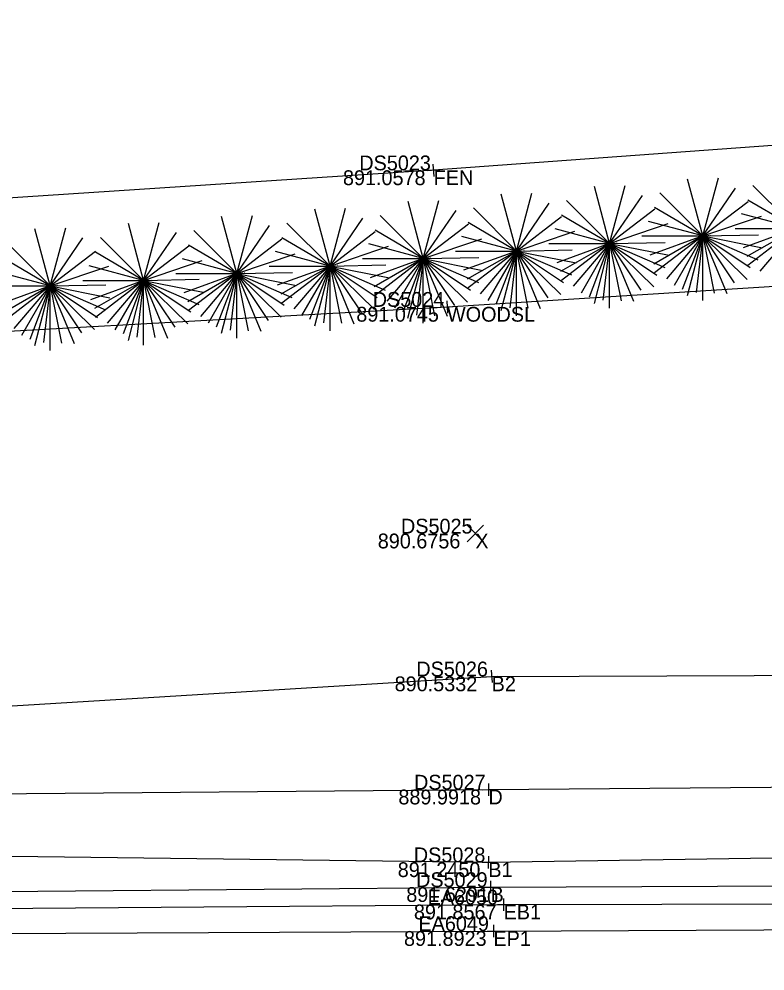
# Model space of a CAD drawing. Extents: x 179044 to 189691, y 286531 to 301257.
# Drawn here: x 179842.3 to 179902.7, y 300591.8 to 300668.9 of the extents above; entities that cross this region are included whole.
import ezdxf

# ---------------------------------------------------------------- set-up
doc = ezdxf.new("R2010")
doc.units = 0
for name, color, linetype in [('DR_X_Ditch', 7, 'Continuous'), ('PV_X_EOP', 7, 'Continuous'), ('PV_X_Shoulder_Aggregate', 7, 'Continuous'), ('RD_X_Fence', 7, 'Continuous'), ('SV_X_Break_Lines', 7, 'Continuous'), ('SV_X_Random_Point', 7, 'Continuous'), ('SV_X_Shot_Marker', 7, 'Continuous'), ('SV_X_Text_Comment', 7, 'Continuous'), ('SV_X_Text_Elevation', 7, 'Continuous'), ('SV_X_Text_Name', 7, 'Continuous'), ('VG_X_Cells', 7, 'Continuous'), ('VG_X_Text', 7, 'Continuous'), ('VG_X_Tree_Line_Rt', 7, 'Continuous')]:
    doc.layers.add(name, color=color, linetype=linetype)

msp = doc.modelspace()

# ---------------------------------------------------------------- linework, layer by layer
at = {"layer": 'DR_X_Ditch'}
msp.add_lwpolyline([(179564.56, 300599.962), (179672.339, 300603.26), (179771.172, 300605.494), (179880.337, 300606.441), (179984.937, 300607.328), (180077.947, 300608.965), (180127.19, 300616.843), (180132.045, 300619.573), (180144.286, 300623.545), (180155.547, 300629.29), (180160.465, 300633.547)], dxfattribs=at)
at = {"layer": 'PV_X_EOP'}
msp.add_lwpolyline([(179370.831, 300591.751), (179475.585, 300592.875), (179659.265, 300594.122), (179770.991, 300594.472), (179880.742, 300594.985), (179984.71, 300595.495), (180079.288, 300595.313), (180129.921, 300597.382), (180139.474, 300598.239), (180154.233, 300602.666), (180170.463, 300611.587), (180179.633, 300620.691), (180184.59, 300626.615), (180188.342, 300633.535), (180190.62, 300639.725), (180171.316, 300693.382), (180137.201, 300785.062), (180098.417, 300888.791)], dxfattribs=at)
at = {"layer": 'PV_X_Shoulder_Aggregate'}
msp.add_lwpolyline([(179563.565, 300594.924), (179658.987, 300595.359), (179770.596, 300596.259), (179881.565, 300597.129), (179984.257, 300597.357), (180079.139, 300597.322), (180129.307, 300600.299), (180139.964, 300601.425), (180153.02, 300605.118), (180169.97, 300613.883), (180177.635, 300623.691), (180181.654, 300635.111), (180182.998, 300649.235), (180167.771, 300692.69), (180134.639, 300784.201), (180095.484, 300888.508)], dxfattribs=at)
at = {"layer": 'RD_X_Fence'}
msp.add_lwpolyline([(180033.616, 300896.161), (180069.423, 300800.637), (180103.118, 300709.458), (180117.129, 300674.9), (180112.616, 300673.011), (180037.359, 300667.77), (179974.547, 300663.799), (179875.902, 300656.609), (179766.558, 300649.439), (179668.068, 300642.7), (179565.54, 300636.358)], dxfattribs=at)
at = {"layer": 'SV_X_Break_Lines'}
for points in [[(179564.638, 300606.986), (179671.768, 300606.922), (179771.087, 300608.912), (179880.599, 300615.611), (179986.884, 300616.02), (180078.033, 300615.521), (180124.742, 300624.492), (180128.289, 300624.221), (180137.303, 300629.118), (180148.459, 300633.708), (180154.503, 300636.496), (180146.307, 300651.241), (180135.969, 300673.811), (180118.542, 300716.074), (180095.911, 300772.35), (180076.611, 300824.96), (180047.5, 300900.199)], [(179564.191, 300598.682), (179770.809, 300601.942), (179880.33, 300600.557), (179984.707, 300602.17), (180076.298, 300602.513), (180129.447, 300605.473), (180133.823, 300610.665), (180143.543, 300612.063), (180154.911, 300619.358), (180168.807, 300625.749), (180172.898, 300631.66), (180174.527, 300641.071), (180168.307, 300660.619), (180157.537, 300688.57), (180123.865, 300779.294), (180087.271, 300883.216)], [(179564.385, 300595.92), (179672.75, 300596.68), (179770.459, 300597.562), (179880.51, 300598.544), (179984.703, 300599.007), (180076.342, 300598.773), (180129.476, 300602.027), (180135.94, 300603.814), (180151.807, 300606.879), (180162.976, 300612.722)]]:
    msp.add_lwpolyline(points, dxfattribs=at)
at = {"layer": 'SV_X_Random_Point'}
for p, q in [((179878.613, 300626.516), (179879.946, 300627.851)), ((179878.613, 300627.851), (179879.946, 300626.516))]:
    msp.add_line(p, q, dxfattribs=at)
at = {"layer": 'SV_X_Shot_Marker'}
for p, q in [((179876.401, 300656.644), (179875.403, 300656.575)), ((179875.936, 300656.11), (179875.867, 300657.108)), ((179875.902, 300656.609), (179875.902, 300656.609)), ((179876.954, 300646.049), (179877.009, 300645.05)), ((179876.482, 300645.522), (179877.481, 300645.577)), ((179876.981, 300645.549), (179876.981, 300645.549)), ((179880.1, 300615.581), (179881.098, 300615.642)), ((179880.569, 300616.11), (179880.63, 300615.112)), ((179880.599, 300615.611), (179880.599, 300615.611)), ((179879.837, 300606.436), (179880.837, 300606.445)), ((179880.332, 300606.941), (179880.341, 300605.941)), ((179880.337, 300606.441), (179880.337, 300606.441)), ((179880.336, 300601.057), (179880.323, 300600.057)), ((179879.83, 300600.563), (179880.83, 300600.55)), ((179880.33, 300600.557), (179880.33, 300600.557)), ((179880.505, 300599.044), (179880.514, 300598.044)), ((179880.01, 300598.54), (179881.01, 300598.549)), ((179880.51, 300598.544), (179880.51, 300598.544)), ((179881.065, 300597.125), (179882.064, 300597.133)), ((179881.561, 300597.629), (179881.568, 300596.629)), ((179881.565, 300597.129), (179881.565, 300597.129)), ((179880.242, 300594.983), (179881.242, 300594.988)), ((179880.74, 300595.485), (179880.745, 300594.485)), ((179880.742, 300594.985), (179880.742, 300594.985))]:
    msp.add_line(p, q, dxfattribs=at)
at = {"layer": 'VG_X_Cells'}
for p, q in [((179897.709, 300651.29), (179896.474, 300655.904)), ((179897.709, 300651.29), (179898.966, 300655.989)), ((179890.158, 300650.681), (179888.923, 300655.294)), ((179890.158, 300650.681), (179891.415, 300655.379)), ((179897.709, 300651.29), (179900.364, 300655.175)), ((179905.26, 300651.9), (179901.77, 300655.386)), ((179875.057, 300649.463), (179876.313, 300654.161)), ((179882.608, 300650.072), (179881.373, 300654.685)), ((179882.608, 300650.072), (179883.864, 300654.77)), ((179890.158, 300650.681), (179886.668, 300654.168)), ((179890.158, 300650.681), (179892.813, 300654.566)), ((179897.709, 300651.29), (179894.219, 300654.777)), ((179897.709, 300651.29), (179901.366, 300654.095)), ((179905.26, 300651.9), (179901.353, 300654.196)), ((179867.506, 300648.854), (179866.271, 300653.467)), ((179867.506, 300648.854), (179868.763, 300653.552)), ((179875.057, 300649.463), (179873.822, 300654.076)), ((179875.057, 300649.463), (179877.712, 300653.348)), ((179882.608, 300650.072), (179879.118, 300653.559)), ((179882.608, 300650.072), (179885.263, 300653.957)), ((179890.158, 300650.681), (179893.815, 300653.486)), ((179897.709, 300651.29), (179893.802, 300653.587)), ((179859.955, 300648.244), (179858.72, 300652.858)), ((179859.955, 300648.244), (179861.212, 300652.943)), ((179867.506, 300648.854), (179870.161, 300652.739)), ((179875.057, 300649.463), (179871.567, 300652.949)), ((179882.608, 300650.072), (179886.264, 300652.877)), ((179890.158, 300650.681), (179886.252, 300652.978)), ((179897.709, 300651.29), (179902.446, 300652.897)), ((179905.26, 300651.9), (179900.847, 300653.083)), ((179844.836, 300647.249), (179843.601, 300651.862)), ((179844.836, 300647.249), (179846.093, 300651.947)), ((179852.4, 300647.692), (179851.165, 300652.305)), ((179852.4, 300647.692), (179853.657, 300652.39)), ((179859.955, 300648.244), (179862.61, 300652.129)), ((179867.506, 300648.854), (179864.016, 300652.34)), ((179875.057, 300649.463), (179878.713, 300652.268)), ((179882.608, 300650.072), (179878.701, 300652.369)), ((179890.158, 300650.681), (179885.745, 300651.864)), ((179890.158, 300650.681), (179894.895, 300652.288)), ((179897.709, 300651.29), (179893.296, 300652.474)), ((179900.325, 300651.9), (179905.26, 300651.9)), ((179905.26, 300651.9), (179900.97, 300650.338)), ((179905.26, 300651.9), (179901.277, 300649.618)), ((179905.26, 300651.9), (179901.353, 300648.905)), ((179905.26, 300651.9), (179902.315, 300648.433)), ((179844.836, 300647.249), (179847.491, 300651.134)), ((179852.4, 300647.692), (179848.91, 300651.178)), ((179852.4, 300647.692), (179855.055, 300651.577)), ((179859.955, 300648.244), (179856.465, 300651.731)), ((179859.955, 300648.244), (179863.612, 300651.049)), ((179867.506, 300648.854), (179863.599, 300651.15)), ((179867.506, 300648.854), (179871.163, 300651.659)), ((179875.057, 300649.463), (179871.15, 300651.759)), ((179875.057, 300649.463), (179879.793, 300651.069)), ((179882.608, 300650.072), (179878.194, 300651.255)), ((179882.608, 300650.072), (179887.344, 300651.679)), ((179892.774, 300651.29), (179897.709, 300651.29)), ((179897.709, 300651.29), (179893.419, 300649.729)), ((179897.709, 300651.29), (179893.726, 300649.009)), ((179897.709, 300651.29), (179893.802, 300648.295)), ((179897.709, 300651.29), (179894.764, 300647.824)), ((179897.709, 300651.29), (179895.391, 300647.275)), ((179897.709, 300651.29), (179896.044, 300646.95)), ((179897.709, 300651.29), (179896.446, 300646.434)), ((179897.709, 300651.29), (179897.167, 300646.699)), ((179897.709, 300651.29), (179902.219, 300651.382)), ((179897.709, 300646.05), (179897.709, 300651.29)), ((179897.709, 300651.29), (179898.631, 300646.654)), ((179897.709, 300651.29), (179899.642, 300646.622)), ((179897.709, 300651.29), (179900.246, 300647.497)), ((179897.709, 300651.29), (179901.297, 300647.769)), ((179897.709, 300651.29), (179901.531, 300648.735)), ((179897.709, 300651.29), (179902.174, 300649.349)), ((179897.709, 300651.29), (179902.537, 300650.332)), ((179844.836, 300647.249), (179841.346, 300650.736)), ((179852.4, 300647.692), (179856.057, 300650.497)), ((179859.955, 300648.244), (179856.049, 300650.541)), ((179867.506, 300648.854), (179872.243, 300650.46)), ((179875.057, 300649.463), (179870.643, 300650.646)), ((179885.223, 300650.681), (179890.158, 300650.681)), ((179890.158, 300650.681), (179885.868, 300649.119)), ((179890.158, 300650.681), (179886.175, 300648.399)), ((179890.158, 300650.681), (179886.252, 300647.686)), ((179890.158, 300650.681), (179887.213, 300647.214)), ((179890.158, 300650.681), (179887.84, 300646.666)), ((179890.158, 300650.681), (179888.493, 300646.341)), ((179890.158, 300650.681), (179888.895, 300645.824)), ((179890.158, 300650.681), (179889.617, 300646.089)), ((179890.158, 300650.681), (179894.668, 300650.773)), ((179890.158, 300645.441), (179890.158, 300650.681)), ((179890.158, 300650.681), (179891.08, 300646.044)), ((179890.158, 300650.681), (179892.092, 300646.013)), ((179890.158, 300650.681), (179892.695, 300646.888)), ((179890.158, 300650.681), (179893.747, 300647.159)), ((179890.158, 300650.681), (179893.98, 300648.126)), ((179890.158, 300650.681), (179894.623, 300648.739)), ((179890.158, 300650.681), (179894.987, 300649.723)), ((179844.836, 300647.249), (179840.93, 300649.546)), ((179844.836, 300647.249), (179848.493, 300650.054)), ((179852.4, 300647.692), (179848.493, 300649.988)), ((179859.955, 300648.244), (179864.692, 300649.851)), ((179867.506, 300648.854), (179863.093, 300650.037)), ((179875.057, 300649.463), (179879.567, 300649.554)), ((179877.673, 300650.072), (179882.608, 300650.072)), ((179882.608, 300650.072), (179878.318, 300648.51)), ((179882.608, 300650.072), (179878.624, 300647.79)), ((179882.608, 300650.072), (179878.701, 300647.077)), ((179882.608, 300650.072), (179879.663, 300646.605)), ((179882.608, 300650.072), (179880.289, 300646.057)), ((179882.608, 300650.072), (179880.943, 300645.732)), ((179882.608, 300650.072), (179881.344, 300645.215)), ((179882.608, 300650.072), (179882.066, 300645.48)), ((179882.608, 300650.072), (179887.118, 300650.164)), ((179882.608, 300644.832), (179882.608, 300650.072)), ((179882.608, 300650.072), (179883.529, 300645.435)), ((179882.608, 300650.072), (179884.541, 300645.404)), ((179882.608, 300650.072), (179885.144, 300646.279)), ((179882.608, 300650.072), (179886.196, 300646.55)), ((179882.608, 300650.072), (179886.429, 300647.517)), ((179882.608, 300650.072), (179887.073, 300648.13)), ((179882.608, 300650.072), (179887.436, 300649.114)), ((179844.836, 300647.249), (179849.573, 300648.856)), ((179852.4, 300647.692), (179847.987, 300648.875)), ((179852.4, 300647.692), (179857.137, 300649.298)), ((179859.955, 300648.244), (179855.542, 300649.428)), ((179862.571, 300648.854), (179867.506, 300648.854)), ((179867.506, 300648.854), (179863.216, 300647.292)), ((179867.506, 300648.854), (179863.523, 300646.572)), ((179867.506, 300648.854), (179863.599, 300645.859)), ((179867.506, 300648.854), (179864.561, 300645.387)), ((179867.506, 300648.854), (179865.188, 300644.839)), ((179867.506, 300648.854), (179865.841, 300644.514)), ((179867.506, 300648.854), (179866.243, 300643.997)), ((179867.506, 300648.854), (179866.964, 300644.262)), ((179867.506, 300648.854), (179872.016, 300648.945)), ((179867.506, 300643.614), (179867.506, 300648.854)), ((179867.506, 300648.854), (179868.428, 300644.217)), ((179867.506, 300648.854), (179869.439, 300644.185)), ((179867.506, 300648.854), (179870.043, 300645.06)), ((179867.506, 300648.854), (179871.094, 300645.332)), ((179867.506, 300648.854), (179871.328, 300646.299)), ((179867.506, 300648.854), (179871.971, 300646.912)), ((179867.506, 300648.854), (179872.334, 300647.895)), ((179870.122, 300649.463), (179875.057, 300649.463)), ((179875.057, 300649.463), (179870.767, 300647.901)), ((179875.057, 300649.463), (179871.073, 300647.181)), ((179875.057, 300649.463), (179871.15, 300646.468)), ((179875.057, 300649.463), (179872.112, 300645.996)), ((179875.057, 300649.463), (179872.738, 300645.448)), ((179875.057, 300649.463), (179873.392, 300645.123)), ((179875.057, 300649.463), (179873.793, 300644.606)), ((179875.057, 300649.463), (179874.515, 300644.871)), ((179875.057, 300644.223), (179875.057, 300649.463)), ((179875.057, 300649.463), (179875.978, 300644.826)), ((179875.057, 300649.463), (179876.99, 300644.794)), ((179875.057, 300649.463), (179877.593, 300645.669)), ((179875.057, 300649.463), (179878.645, 300645.941)), ((179875.057, 300649.463), (179878.878, 300646.908)), ((179875.057, 300649.463), (179879.522, 300647.521)), ((179875.057, 300649.463), (179879.885, 300648.504)), ((179844.836, 300647.249), (179840.423, 300648.432)), ((179855.02, 300648.244), (179859.955, 300648.244)), ((179859.955, 300648.244), (179855.665, 300646.683)), ((179859.955, 300648.244), (179855.972, 300645.963)), ((179859.955, 300648.244), (179856.049, 300645.249)), ((179859.955, 300648.244), (179857.01, 300644.778)), ((179859.955, 300648.244), (179857.637, 300644.229)), ((179859.955, 300648.244), (179858.29, 300643.904)), ((179859.955, 300648.244), (179858.692, 300643.388)), ((179859.955, 300648.244), (179859.414, 300643.653)), ((179859.955, 300648.244), (179864.465, 300648.336)), ((179859.955, 300643.004), (179859.955, 300648.244)), ((179859.955, 300648.244), (179860.877, 300643.608)), ((179859.955, 300648.244), (179861.889, 300643.576)), ((179859.955, 300648.244), (179862.492, 300644.451)), ((179859.955, 300648.244), (179863.544, 300644.723)), ((179859.955, 300648.244), (179863.777, 300645.689)), ((179859.955, 300648.244), (179864.42, 300646.303)), ((179859.955, 300648.244), (179864.784, 300647.286)), ((179839.901, 300647.249), (179844.836, 300647.249)), ((179844.836, 300647.249), (179840.546, 300645.687)), ((179844.836, 300647.249), (179840.853, 300644.967)), ((179844.836, 300647.249), (179840.93, 300644.254)), ((179844.836, 300647.249), (179841.891, 300643.782)), ((179844.836, 300647.249), (179842.518, 300643.234)), ((179844.836, 300647.249), (179843.171, 300642.909)), ((179844.836, 300647.249), (179843.573, 300642.392)), ((179844.836, 300647.249), (179844.295, 300642.657)), ((179844.836, 300647.249), (179849.346, 300647.341)), ((179844.836, 300642.009), (179844.836, 300647.249)), ((179844.836, 300647.249), (179845.758, 300642.612)), ((179844.836, 300647.249), (179846.77, 300642.581)), ((179844.836, 300647.249), (179847.373, 300643.456)), ((179844.836, 300647.249), (179848.425, 300643.727)), ((179844.836, 300647.249), (179848.658, 300644.694)), ((179844.836, 300647.249), (179849.301, 300645.307)), ((179844.836, 300647.249), (179849.665, 300646.291)), ((179847.465, 300647.692), (179852.4, 300647.692)), ((179852.4, 300647.692), (179848.11, 300646.13)), ((179852.4, 300647.692), (179848.417, 300645.41)), ((179852.4, 300647.692), (179848.493, 300644.697)), ((179852.4, 300647.692), (179849.455, 300644.225)), ((179852.4, 300647.692), (179850.082, 300643.677)), ((179852.4, 300647.692), (179850.735, 300643.352)), ((179852.4, 300647.692), (179851.137, 300642.835)), ((179852.4, 300647.692), (179851.858, 300643.1)), ((179852.4, 300647.692), (179856.91, 300647.783)), ((179852.4, 300642.452), (179852.4, 300647.692)), ((179852.4, 300647.692), (179853.322, 300643.055)), ((179852.4, 300647.692), (179854.333, 300643.023)), ((179852.4, 300647.692), (179854.937, 300643.898)), ((179852.4, 300647.692), (179855.988, 300644.17)), ((179852.4, 300647.692), (179856.222, 300645.137)), ((179852.4, 300647.692), (179856.865, 300645.75)), ((179852.4, 300647.692), (179857.228, 300646.733))]:
    msp.add_line(p, q, dxfattribs=at)
at = {"layer": 'VG_X_Tree_Line_Rt'}
msp.add_lwpolyline([(179653.026, 300638.702), (179657.624, 300631.959), (179767.935, 300639.504), (179876.981, 300645.549), (179982.655, 300652.223), (180074.045, 300659.112), (180113.167, 300662.01), (180119.55, 300662.124), (180124.383, 300666.201), (180126.147, 300679.098), (180114.54, 300714.374), (180093.362, 300771.604), (180073.514, 300824.308), (180043.465, 300899.612)], dxfattribs=at)

# ---------------------------------------------------------------- texts
at = {"layer": 'SV_X_Text_Comment'}
for s, height, p in [('FEN', 1.2, (179875.902, 300655.409)), ('TE', 0.12, (179897.709, 300651.17)), ('TE', 0.12, (179890.158, 300650.561)), ('TE', 0.12, (179882.608, 300649.952)), ('TE', 0.12, (179867.506, 300648.734)), ('TE', 0.12, (179875.057, 300649.343)), ('TE', 0.12, (179859.955, 300648.124)), ('TE', 0.12, (179844.836, 300647.129)), ('TE', 0.12, (179852.4, 300647.572)), ('WOODSL', 1.2, (179876.981, 300644.349)), ('X', 1.2, (179879.279, 300625.983)), ('B2', 1.2, (179880.599, 300614.411)), ('D', 1.2, (179880.337, 300605.241)), ('B1', 1.2, (179880.33, 300599.357)), ('B', 1.2, (179880.51, 300597.344)), ('EB1', 1.2, (179881.565, 300595.929)), ('EP1', 1.2, (179880.742, 300593.785))]:
    msp.add_text(s, height=height, dxfattribs=at).set_placement(p)
at = {"layer": 'SV_X_Text_Elevation'}
for s, p in [('891.0578', (179868.552, 300655.409)), ('891.0745', (179869.631, 300644.349)), ('890.6756', (179871.371, 300625.983)), ('890.5332', (179872.738, 300614.411)), ('889.9918', (179873.043, 300605.241)), ('891.2450', (179872.989, 300599.357)), ('891.6291', (179873.682, 300597.344)), ('891.8567', (179874.299, 300595.929)), ('891.8923', (179873.496, 300593.785))]:
    msp.add_text(s, height=1.2, dxfattribs=at).set_placement(p)
at = {"layer": 'SV_X_Text_Name'}
for s, p in [('DS5023', (179869.874, 300656.609)), ('DS5024', (179870.963, 300645.549)), ('DS5025', (179873.252, 300627.183)), ('DS5026', (179874.496, 300615.611)), ('DS5027', (179874.309, 300606.441)), ('DS5028', (179874.292, 300600.557)), ('DS5029', (179874.473, 300598.544)), ('EA6050', (179875.404, 300597.129)), ('EA6049', (179874.667, 300594.985))]:
    msp.add_text(s, height=1.2, dxfattribs=at).set_placement(p)
at = {"layer": 'VG_X_Text'}
for p in [(179897.709, 300651.29), (179890.158, 300650.681), (179875.057, 300649.463), (179882.608, 300650.072), (179867.506, 300648.854), (179859.955, 300648.244), (179844.836, 300647.249), (179852.4, 300647.692)]:
    msp.add_text(' NOTE:8', height=0.12, dxfattribs=at).set_placement(p)

doc.saveas('drawing.dxf')
